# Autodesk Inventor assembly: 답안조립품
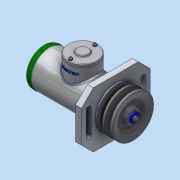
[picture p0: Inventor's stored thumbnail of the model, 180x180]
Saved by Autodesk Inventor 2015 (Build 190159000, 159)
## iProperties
Created: 2017-10
Part Number: 답안조립품
Document SubType Name: Assembly
Designer: SCD-A08
Author: SCD-A08
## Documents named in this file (20)
- C:\Users\SCD-A08\Desktop\471007V1003\답안조립품.iam
- C:\Users\SCD-A08\Desktop\471007V1003\본체.ipt
- C:\Users\SCD-A08\Desktop\471007V1003\V-벨트풀리.ipt
- C:\Users\SCD-A08\Desktop\471007V1003\너트 M10.ipt
- C:\Users\SCD-A08\Desktop\471007V1003\멈춤링 15 x 1.ipt
- C:\Users\SCD-A08\Desktop\471007V1003\멈춤링 35x1.6.ipt
- C:\Users\SCD-A08\Desktop\471007V1003\베어링 15 x 35 x 11.ipt
- C:\Users\SCD-A08\Desktop\471007V1003\볼트 M4 x 10.ipt
- C:\Users\SCD-A08\Desktop\471007V1003\부시1.ipt
- C:\Users\SCD-A08\Desktop\471007V1003\부시2.ipt
- C:\Users\SCD-A08\Desktop\471007V1003\사이드 커버.ipt
- 사이드 커버.ipt
- C:\Users\SCD-A08\Desktop\471007V1003\십자볼트 M3 x 10.ipt
- C:\Users\SCD-A08\Desktop\471007V1003\오일 실 15 25 7.ipt
- C:\Users\SCD-A08\Desktop\471007V1003\와셔 3x6.ipt
- C:\Users\SCD-A08\Desktop\471007V1003\와셔 4x16.ipt
- C:\Users\SCD-A08\Desktop\471007V1003\와셔 10x21.ipt
- C:\Users\SCD-A08\Desktop\471007V1003\축.ipt
- C:\Users\SCD-A08\Desktop\471007V1003\키 4 x 4 x 18.ipt
- C:\Users\SCD-A08\Desktop\471007V1003\탑 커버.ipt
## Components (2 placed, 2 different names)
1. V-벨트풀리:1 — 각도:2
2. ISO 4017 M4 x 10:1
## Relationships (1: Angle 1)
- 각도:2 [Angle]: V-벨트풀리:1
